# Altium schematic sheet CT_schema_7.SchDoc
size 277 x 170 mm
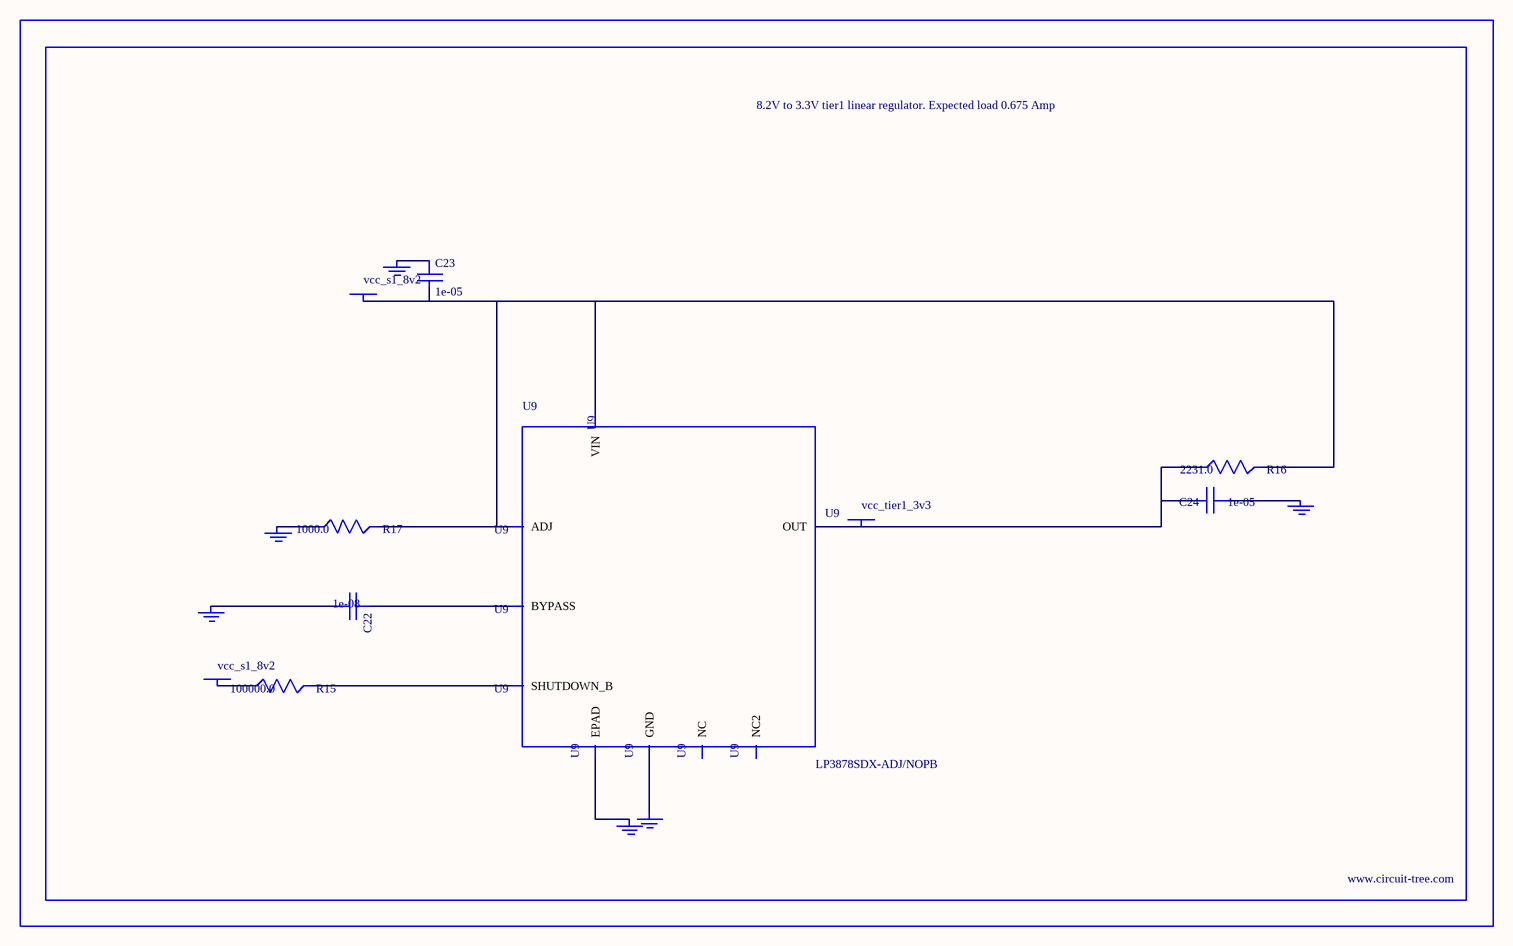
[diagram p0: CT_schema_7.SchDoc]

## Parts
BORDER6  (no value)
C22  1e-08  [C0402]
C23  1e-05  [C1206]
C24  1e-05  [C1210]
GND_INSTANCE_6_0  (no value)
GND_INSTANCE_6_1  (no value)
GND_INSTANCE_6_2  (no value)
GND_INSTANCE_6_3  (no value)
GND_INSTANCE_6_4  (no value)
GND_INSTANCE_6_5  (no value)
POWER_INSTANCE_6_0  vcc_s1_8v2
POWER_INSTANCE_6_1  vcc_s1_8v2
POWER_INSTANCE_6_2  vcc_tier1_3v3
R15  100000.0  [R0603]
R16  2231.0  [R0603]
R17  1000.0  [R0603]
U9  LP3878SDX-ADJ/NOPB  [WSON-8]

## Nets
NetC22_1: C22.1 U9.1(BYPASS)
NetC22_2: C22.2 GND_INSTANCE_6_0.0(GND)
NetC23_1: C23.1 GND_INSTANCE_6_1.0(GND)
NetC23_2: C23.2 POWER_INSTANCE_6_0.0(PWR) R16.2 R17.2 U9.4(VIN) U9.6(ADJ)
NetC24_1: C24.1 GND_INSTANCE_6_2.0(GND)
NetC24_2: C24.2 POWER_INSTANCE_6_2.0(PWR) R16.1 U9.5(OUT)
NetGND_INSTANCE_6_3_0: GND_INSTANCE_6_3.0(GND) R17.1
NetGND_INSTANCE_6_4_0: GND_INSTANCE_6_4.0(GND) U9.PAD(EPAD)
NetGND_INSTANCE_6_5_0: GND_INSTANCE_6_5.0(GND) U9.3(GND)
NetPOWER_INSTANCE_6_1_0: POWER_INSTANCE_6_1.0(PWR) R15.1
NetR15_2: R15.2 U9.8(SHUTDOWN_B)

Not connected (* = marked no-connect by the designer): U9 2(NC) 7(NC2)

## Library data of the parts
BORDER6 = BORDER_PAGE6
C22 = C0402C103K3RAC
C23 = C1206C106K3RACTU
C24 = GRM32DR61E106MA12L
GND_INSTANCE_6_0-GND_INSTANCE_6_5 = GND
POWER_INSTANCE_6_0-POWER_INSTANCE_6_2 = PWR
R15 = RC0603JR-07100KL
R16 = R16
R17 = RC0603JR-071KL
